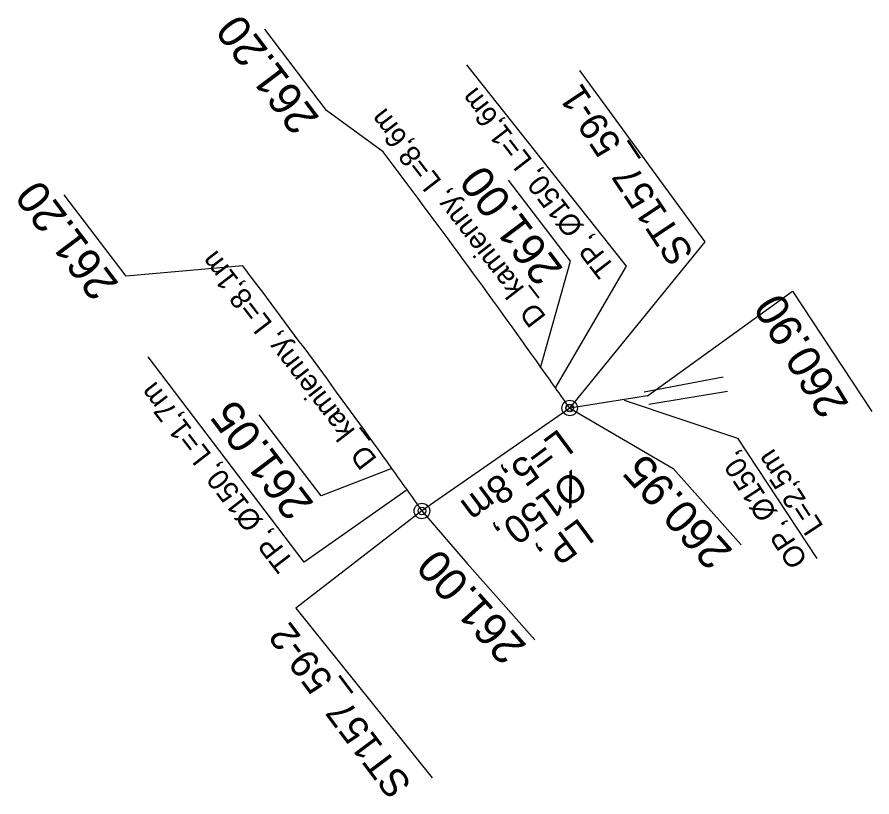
# Model space of a CAD drawing. Extents: x -1 to 65640748, y -22 to 5530284.
# Drawn here: x 6559226 to 6559253.56, y 5528818.81 to 5528843.96 of the extents above; entities that cross this region are included whole.
import ezdxf

# ---------------------------------------------------------------- set-up
doc = ezdxf.new("R2010")
doc.units = 0
for name, color, linetype in [('TOR_PROF-studnie i osadniki', 7, 'Continuous'), ('TOR_PS_ODW-drenaze', 7, 'Continuous'), ('TOR_PS_ODW-drenokolektory', 7, 'Continuous'), ('TOR_PS_ODW-kolektory', 7, 'Continuous'), ('TOR_PS_ODW-studnie PEHD', 7, 'Continuous'), ('TOR_PS_OPIS_O-opisy rurociagow', 7, 'Continuous'), ('TOR_PS_OPIS_O-opisy studni', 7, 'Continuous'), ('TOR_PS_OPIS_T-INFO', 7, 'Continuous'), ('TOR_PS_T-rowy otwarte umocnione', 7, 'Continuous')]:
    doc.layers.add(name, color=color, linetype=linetype)

msp = doc.modelspace()

# ---------------------------------------------------------------- linework, layer by layer
at = {"layer": 'TOR_PROF-studnie i osadniki'}
for centre, radius in [((6559243.819, 5528831.351), 0.25), ((6559243.819, 5528831.351), 0.125), ((6559239.053, 5528828.034), 0.25), ((6559239.053, 5528828.034), 0.125)]:
    msp.add_circle(centre, radius, dxfattribs=at)
at = {"layer": 'TOR_PS_ODW-drenaze'}
for centre, radius, start, end in [((6558998.613, 5528659.204), 299.6, 35.3756, 37.02521), ((6558998.653, 5528658.104), 294.4, 35.58127, 37.16063)]:
    msp.add_arc(centre, radius, start, end, dxfattribs=at)
at = {"layer": 'TOR_PS_ODW-drenokolektory'}
msp.add_lwpolyline([(6559243.819, 5528831.351), (6559243.819, 5528831.351), (6559239.053, 5528828.034), (6559239.053, 5528828.034)], dxfattribs=at)
for centre, radius, start, end in [((6558998.613, 5528659.204), 299.6, 35.0708, 35.3756), ((6558998.653, 5528658.104), 294.4, 35.25501, 35.58127)]:
    msp.add_arc(centre, radius, start, end, dxfattribs=at)
at = {"layer": 'TOR_PS_ODW-kolektory'}
msp.add_line((6559246.325, 5528831.749), (6559243.819, 5528831.351), dxfattribs=at)
at = {"layer": 'TOR_PS_ODW-studnie PEHD'}
for radius in [0.25, 0.112]:
    msp.add_circle((6559243.819, 5528831.351), radius, dxfattribs=at)
at = {"layer": 'TOR_PS_OPIS_T-INFO'}
for points in [[(6559237.805, 5528839.613), (6559235.981, 5528840.948), (6559233.989, 5528843.569)], [(6559243.36, 5528832.002), (6559245.655, 5528835.93), (6559240.502, 5528842.419)], [(6559243.819, 5528831.351), (6559248.189, 5528836.715), (6559244.143, 5528842.232)], [(6559242.878, 5528832.651), (6559243.841, 5528836.082), (6559241.849, 5528838.704)], [(6559233.274, 5528835.937), (6559229.511, 5528835.602), (6559227.518, 5528838.224)], [(6559246.325, 5528831.749), (6559251.006, 5528835.124), (6559253.564, 5528831.242)], [(6559238.573, 5528828.72), (6559235.251, 5528826.381), (6559230.22, 5528833.002)], [(6559245.574, 5528831.611), (6559249.229, 5528830.382), (6559251.787, 5528826.5)], [(6559238.086, 5528829.403), (6559235.801, 5528828.517), (6559233.808, 5528831.138)], [(6559243.819, 5528831.351), (6559247.158, 5528829.399), (6559249.348, 5528826.94)], [(6559239.053, 5528828.034), (6559234.991, 5528824.896), (6559239.385, 5528819.433)], [(6559239.053, 5528828.034), (6559240.507, 5528826.337), (6559242.698, 5528823.878)]]:
    msp.add_lwpolyline(points, dxfattribs=at)
at = {"layer": 'TOR_PS_T-rowy otwarte umocnione'}
for p, q in [((6559248.766, 5528832.347), (6559246.225, 5528831.865)), ((6559248.91, 5528831.89), (6559246.37, 5528831.464))]:
    msp.add_line(p, q, dxfattribs=at)

# ---------------------------------------------------------------- texts
at = {"layer": 'TOR_PS_OPIS_O-opisy rurociagow'}
for s, height, rotation, p in [('TP, Ø150, L=1,6m', 0.675, 127.6287, (6559245.308, 5528835.881)), ('D_kamienny, L=8,6m', 0.675, 127.6287, (6559243.084, 5528834.294)), ('D_kamienny, L=8,1m', 0.675, 127.6287, (6559237.63, 5528829.706)), ('TP, Ø150, L=1,7m', 0.675, 127.6287, (6559234.958, 5528826.388)), ('L=5,8m', 0.9, 216.6656, (6559243.48, 5528830.71)), ('L=2,5m', 0.675, 122.9857, (6559252.023, 5528827.537)), ('OP, Ø150, ', 0.675, 122.9857, (6559251.517, 5528826.458)), ('Ø150, ', 0.9, 216.6656, (6559243.951, 5528829.378)), ('LP, ', 0.9, 216.6656, (6559244.141, 5528827.836))]:
    msp.add_text(s, height=height, rotation=rotation, dxfattribs=at).set_placement(p)
at = {"layer": 'TOR_PS_OPIS_O-opisy studni'}
for s, rotation, p in [('ST157_59-1', 123.5513, (6559247.849, 5528836.342)), ('ST157_59-2', 126.8851, (6559238.755, 5528819.213))]:
    msp.add_text(s, height=0.9, rotation=rotation, dxfattribs=at).set_placement(p)
at = {"layer": 'TOR_PS_OPIS_T-INFO'}
for s, rotation, p in [('261.20', 127.025, (6559235.774, 5528840.699)), ('261.00', 127.025, (6559243.634, 5528835.834)), ('261.20', 127.025, (6559229.304, 5528835.353)), ('260.90', 121.3795, (6559252.843, 5528831.467)), ('261.05', 127.025, (6559235.596, 5528828.266)), ('260.95', 131.895, (6559249.112, 5528826.748)), ('261.00', 131.895, (6559242.46, 5528823.689))]:
    msp.add_text(s, height=1.05, rotation=rotation, dxfattribs=at).set_placement(p)

doc.saveas('drawing.dxf')
